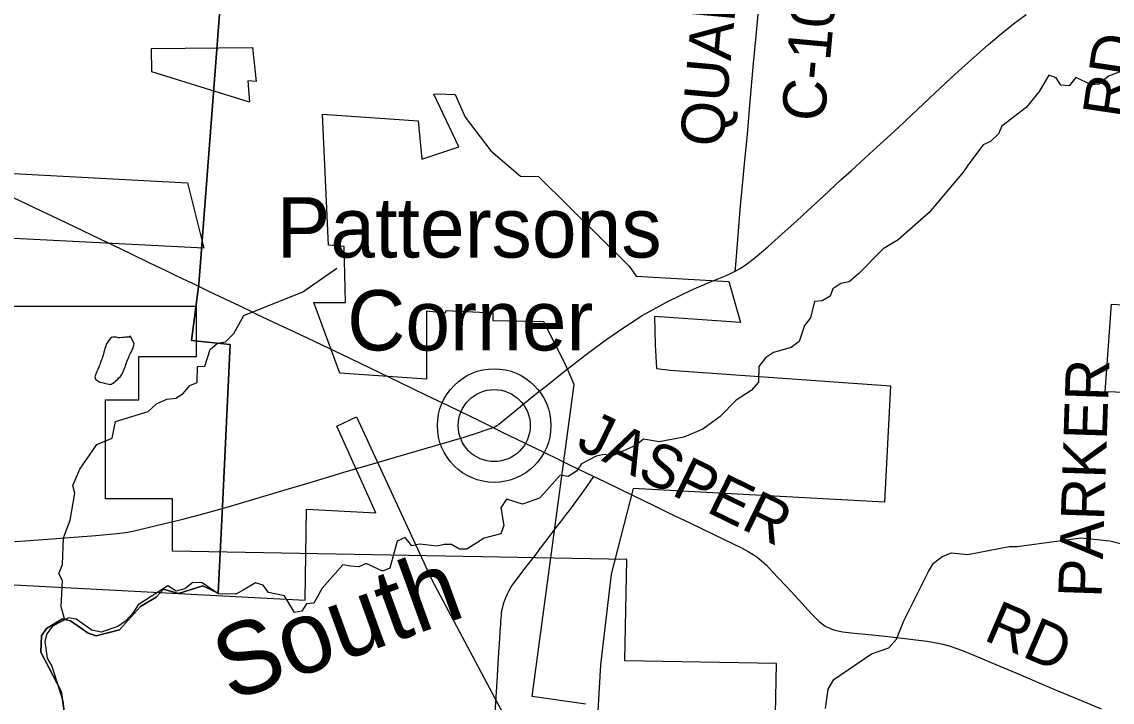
# Model space of a CAD drawing. Extents: x -5.4 to 49.9, y 13.2 to 48.4.
# Drawn here: x 27.015 to 28.445, y 41.82 to 42.711 of the extents above; entities that cross this region are included whole.
import ezdxf

# ---------------------------------------------------------------- set-up
doc = ezdxf.new("R2010")
doc.units = 0
for name, color, linetype in [('GM_X_Corporation', 7, 'Continuous'), ('GM_X_County_Road', 7, 'Continuous'), ('GM_X_County_Road_Text', 7, 'Continuous'), ('GM_X_Minor_Lake', 7, 'Continuous'), ('GM_X_Minor_River', 7, 'Continuous'), ('GM_X_Minor_River_Text', 7, 'Continuous'), ('GM_X_Township', 7, 'Continuous'), ('GM_X_Township_Road_Text', 7, 'Continuous'), ('GM_X_Unincorporated', 7, 'Continuous'), ('GM_X_Unincorporated_Location', 7, 'Continuous'), ('GM_X_Unincorporated_Text', 7, 'Continuous')]:
    doc.layers.add(name, color=color, linetype=linetype)

msp = doc.modelspace()

# ---------------------------------------------------------------- linework, layer by layer
at = {"layer": 'GM_X_Corporation'}
for points in [[(27.3179, 42.6776), (27.3227, 42.6332), (27.3114, 42.6342), (27.3139, 42.6063), (27.1858, 42.6457), (27.1855, 42.6766), (27.3179, 42.6776)], [(27.7547, 41.8177), (27.6842, 41.8275), (27.7383, 42.2266), (27.7396, 42.2365), (27.7326, 42.2523), (27.7276, 42.2635), (27.6995, 42.3184), (27.6331, 42.3196), (27.6333, 42.3298), (27.5711, 42.333), (27.5703, 42.3297), (27.546, 42.3323), (27.546, 42.2431), (27.4321, 42.251), (27.3983, 42.3438), (27.4398, 42.3438), (27.4377, 42.4172), (27.4172, 42.419), (27.4093, 42.5906), (27.5351, 42.5819), (27.5396, 42.5315), (27.5882, 42.5476), (27.5553, 42.6165), (27.5599, 42.617), (27.5835, 42.616), (27.5966, 42.5866)], [(27.5966, 42.5866), (27.63, 42.5423), (27.6693, 42.5093), (27.6928, 42.5086), (27.8115, 42.3913), (27.8208, 42.3784), (27.9422, 42.3712), (27.9575, 42.3177), (27.8449, 42.3255), (27.8455, 42.2886), (27.8472, 42.2574), (27.8654, 42.2549), (28.1544, 42.2346), (28.1464, 42.0821), (27.817, 42.1), (27.7879, 41.9878), (27.7742, 41.8691), (27.7695, 41.7935)], [(26.7591, 42.5258), (27.2326, 42.5005), (27.2539, 42.415), (26.7558, 42.4403), (26.7591, 42.5258)], [(28.0022, 41.7383), (28.0047, 41.8708), (27.8059, 41.8745), (27.8083, 42.007), (27.2127, 42.0179), (27.2127, 42.0867), (27.1248, 42.0867), (27.1248, 42.2164), (27.1687, 42.2164), (27.1687, 42.2732), (27.2441, 42.2732), (27.2441, 42.3385), (26.9242, 42.3385)], [(28.5454, 42.223), (28.4358, 42.2265), (28.4438, 42.3414), (28.5393, 42.3357)], [(26.2655, 42.0542), (26.5579, 42.0391), (26.5676, 42.1776), (26.7474, 42.1619), (26.7396, 41.9878), (27.3866, 41.954), (27.3887, 42.0728), (27.4795, 42.068), (27.4285, 42.1818), (27.4542, 42.1938), (27.5529, 41.9806), (27.6747, 41.7515)]]:
    msp.add_lwpolyline(points, dxfattribs=at)
at = {"layer": 'GM_X_County_Road'}
for points in [[(27.9506, 42.3848), (27.9508, 42.3879), (27.9547, 42.437), (27.9573, 42.4655), (27.9633, 42.5298), (27.9665, 42.5638), (27.9699, 42.6022), (27.9748, 42.6574), (27.9784, 42.6975), (27.9843, 42.7606), (27.99, 42.8237), (28.0003, 42.9413), (28.0078, 43.0236), (28.0101, 43.0491)], [(27.9506, 42.3848), (27.957, 42.3884), (27.9643, 42.3931), (27.9704, 42.3975), (27.9768, 42.4026), (27.9933, 42.4167), (28.016, 42.437), (28.0312, 42.4508), (28.0459, 42.4642), (28.0596, 42.4768), (28.0737, 42.4899), (28.0893, 42.5042), (28.103, 42.5168), (28.12, 42.5322), (28.1315, 42.5427), (28.1503, 42.5598), (28.165, 42.5733), (28.2056, 42.6117), (28.2193, 42.6244), (28.2334, 42.6375), (28.2476, 42.6505), (28.2674, 42.6683), (28.2829, 42.6818), (28.2995, 42.6958), (28.3154, 42.7086), (28.3319, 42.7208)], [(26.5924, 42.678), (26.5999, 42.6744), (26.6448, 42.6531), (26.6945, 42.6289), (26.7398, 42.6071), (26.7807, 42.5876), (26.8083, 42.5746), (26.834, 42.5623), (26.8594, 42.5506), (26.8739, 42.5435), (26.9008, 42.5307), (26.9225, 42.52), (26.9392, 42.5118), (26.974, 42.4954), (27.0313, 42.4683), (27.0627, 42.4533), (27.1166, 42.4277), (27.1357, 42.4186), (27.1569, 42.4083), (27.1826, 42.3958), (27.2039, 42.3856), (27.2146, 42.3806), (27.2331, 42.3717), (27.2381, 42.3693)], [(27.6331, 42.18), (27.6365, 42.1815), (27.6381, 42.1824), (27.6394, 42.1832), (27.6407, 42.1842), (27.6617, 42.2012), (27.6818, 42.2179), (27.6866, 42.2218), (27.7037, 42.2351), (27.7265, 42.2534), (27.7535, 42.2743), (27.7674, 42.2847), (27.7825, 42.2956), (27.8061, 42.3118), (27.8195, 42.3207), (27.8278, 42.3261), (27.843, 42.3346), (27.8605, 42.344), (27.8793, 42.3535), (27.8928, 42.3598), (27.903, 42.3644), (27.9225, 42.3725), (27.938, 42.3788), (27.9443, 42.3816), (27.9505, 42.3847), (27.9506, 42.3848)], [(27.2381, 42.3693), (27.261, 42.3581), (27.2879, 42.3454), (27.3003, 42.3396), (27.3182, 42.331), (27.3214, 42.3294)], [(27.3214, 42.3294), (27.3377, 42.3214), (27.3574, 42.3122), (27.3726, 42.3052), (27.4344, 42.276), (27.4708, 42.2585), (27.5106, 42.2394), (27.5447, 42.2229), (27.575, 42.2083), (27.6158, 42.1886), (27.6331, 42.18)], [(27.2778, 42.074), (27.2843, 42.0758), (27.3355, 42.0909), (27.3617, 42.0988), (27.3933, 42.1081), (27.4361, 42.1209), (27.4755, 42.1325), (27.5201, 42.1457), (27.5953, 42.1674), (27.6155, 42.1737), (27.6214, 42.1759), (27.6331, 42.18)], [(27.6331, 42.18), (27.6451, 42.1738), (27.6743, 42.1601), (27.7005, 42.1472), (27.7184, 42.1385), (27.7334, 42.1312), (27.7552, 42.1205), (27.7654, 42.1157)], [(27.6337, 41.7711), (27.6367, 41.8207), (27.6383, 41.8468), (27.6399, 41.8709), (27.6408, 41.8858), (27.6412, 41.8914), (27.6419, 41.9038), (27.6425, 41.9125), (27.6429, 41.9186), (27.6431, 41.9217), (27.6433, 41.9268), (27.6437, 41.9304), (27.644, 41.9341), (27.6443, 41.9372), (27.6448, 41.9401), (27.6453, 41.9429), (27.6458, 41.9449), (27.6464, 41.9472), (27.6473, 41.9501), (27.6499, 41.9571), (27.6521, 41.9621), (27.6543, 41.9665), (27.657, 41.9713), (27.6594, 41.9749), (27.6641, 41.9813), (27.675, 41.9956), (27.6895, 42.0142), (27.6921, 42.0177), (27.6936, 42.0197), (27.6969, 42.0242), (27.6992, 42.0271), (27.7026, 42.0315), (27.7147, 42.0472), (27.7182, 42.0516), (27.7217, 42.056), (27.7296, 42.0663), (27.7334, 42.0713), (27.7359, 42.0748), (27.7429, 42.0843), (27.7465, 42.0893), (27.7491, 42.0928), (27.752, 42.0969), (27.7546, 42.1003), (27.7573, 42.1044), (27.7594, 42.1075), (27.7604, 42.1089), (27.7654, 42.1157)], [(27.7654, 42.1157), (27.7793, 42.1091), (27.8016, 42.0983), (27.8455, 42.077)], [(27.0057, 42.0307), (27.0201, 42.0316), (27.0659, 42.0348), (27.1123, 42.0385), (27.1397, 42.041), (27.1476, 42.0419), (27.1537, 42.0428), (27.1648, 42.0449), (27.1912, 42.0515), (27.2262, 42.0601), (27.2562, 42.0679), (27.2778, 42.074)], [(27.8455, 42.077), (27.8631, 42.0684), (27.891, 42.0549), (27.9224, 42.0398), (27.9587, 42.0222), (27.9676, 42.0176), (27.9741, 42.0138), (27.9792, 42.0102), (27.9846, 42.0059), (27.9915, 41.9995), (27.9997, 41.991), (28.0242, 41.9645), (28.0335, 41.9545), (28.0507, 41.9357), (28.0554, 41.9309), (28.0609, 41.9259), (28.0645, 41.9228), (28.068, 41.9203), (28.071, 41.9186), (28.0736, 41.9174), (28.0772, 41.916), (28.0814, 41.9147), (28.0853, 41.9138), (28.0919, 41.9125), (28.1028, 41.911), (28.1395, 41.9074), (28.1661, 41.9046), (28.1839, 41.9024), (28.2024, 41.8999), (28.2147, 41.8978), (28.2227, 41.8961), (28.2311, 41.8938), (28.2412, 41.8905), (28.2517, 41.8866), (28.2718, 41.8783), (28.2924, 41.8694), (28.3187, 41.8584), (28.3685, 41.8374), (28.4063, 41.8214), (28.4304, 41.8113)]]:
    msp.add_lwpolyline(points, dxfattribs=at)
at = {"layer": 'GM_X_Minor_Lake'}
msp.add_lwpolyline([(27.1576, 42.2997), (27.1561, 42.2985), (27.1538, 42.2982), (27.1512, 42.2982), (27.1493, 42.2978), (27.1474, 42.2979), (27.1439, 42.2975), (27.1417, 42.2975), (27.1394, 42.2983), (27.1375, 42.2983), (27.1348, 42.2984), (27.1322, 42.298), (27.1299, 42.295), (27.1264, 42.2897), (27.1248, 42.2856), (27.1241, 42.2833), (27.1237, 42.2814), (27.1229, 42.2787), (27.1225, 42.2765), (27.1217, 42.2746), (27.1209, 42.2727), (27.1205, 42.2704), (27.1193, 42.2678), (27.1182, 42.264), (27.1174, 42.2621), (27.1166, 42.2602), (27.115, 42.256), (27.1139, 42.2542), (27.1131, 42.2523), (27.1108, 42.2462), (27.1119, 42.2432), (27.1149, 42.2412), (27.1175, 42.2393), (27.1202, 42.2389), (27.1232, 42.2381), (27.127, 42.2373), (27.1296, 42.2369), (27.1315, 42.2365), (27.1342, 42.2376), (27.1361, 42.2391), (27.138, 42.2406), (27.1411, 42.2432), (27.1426, 42.2451), (27.1445, 42.247), (27.1469, 42.2504), (27.148, 42.253), (27.15, 42.2576), (27.1511, 42.2602), (27.1515, 42.2625), (27.1539, 42.2685), (27.1554, 42.2716), (27.1558, 42.2738), (27.1574, 42.2765), (27.1585, 42.2788), (27.1601, 42.2818), (27.1612, 42.2837), (27.1621, 42.2878), (27.1625, 42.2897), (27.1576, 42.2997)], dxfattribs=at)
at = {"layer": 'GM_X_Minor_River'}
for points in [[(28.4608, 42.6479), (28.4402, 42.6403), (28.428, 42.6298), (28.4177, 42.6288), (28.397, 42.6386), (28.3885, 42.6274), (28.3775, 42.6283), (28.3716, 42.6379), (28.3618, 42.6414), (28.3493, 42.62), (28.3319, 42.599), (28.3001, 42.5748), (28.2958, 42.5646), (28.2854, 42.5545), (28.2758, 42.5501), (28.2584, 42.5269), (28.2495, 42.5145), (28.2047, 42.4616), (28.1643, 42.4258), (28.1444, 42.414), (28.1121, 42.3814), (28.0998, 42.371), (28.0891, 42.3685), (28.0788, 42.3618), (28.0752, 42.352), (28.0645, 42.3457), (28.0546, 42.3451), (28.0494, 42.3236), (28.0413, 42.3134), (28.0345, 42.2927), (28.0241, 42.2849), (28.0009, 42.2784), (27.9902, 42.2713), (27.9817, 42.2601), (27.981, 42.2392), (27.9717, 42.2283), (27.9518, 42.2157), (27.931, 42.1944), (27.908, 42.1777), (27.8832, 42.1674), (27.8508, 42.1611), (27.8304, 42.1648), (27.8208, 42.157), (27.7895, 42.1427), (27.7789, 42.1447), (27.7683, 42.1426), (27.7492, 42.1326), (27.7426, 42.1229), (27.7315, 42.1158), (27.7213, 42.1175), (27.7035, 42.0977), (27.6942, 42.0872), (27.6718, 42.0795), (27.6506, 42.0859), (27.6432, 42.0747), (27.6471, 42.0515), (27.6431, 42.0405), (27.6214, 42.0351), (27.5988, 42.0207), (27.5889, 42.0205), (27.5788, 42.0267), (27.5689, 42.0265), (27.5594, 42.0247), (27.5371, 42.0273), (27.5268, 42.0248), (27.5179, 42.036), (27.5072, 42.0312), (27.4979, 41.9956), (27.488, 41.992), (27.4669, 42.0018), (27.457, 41.9974), (27.446, 41.9983), (27.4362, 42), (27.4092, 41.9693), (27.3983, 41.9497), (27.3884, 41.9491), (27.3822, 41.9393), (27.3727, 41.9376), (27.3597, 41.9594), (27.3389, 41.9639), (27.3319, 41.9735), (27.3217, 41.9767), (27.3056, 41.9671), (27.2957, 41.9615), (27.2729, 41.9619), (27.2519, 41.9766)], [(27.0717, 41.9282), (27.0668, 41.9449), (27.0684, 41.9794), (27.0637, 41.9889), (27.0684, 42.0006), (27.0701, 42.0355), (27.0787, 42.0585), (27.0846, 42.0941), (27.0821, 42.104), (27.0915, 42.1255), (27.1136, 42.1578), (27.1339, 42.1659), (27.138, 42.1878), (27.181, 42.2008), (27.1918, 42.2109), (27.2056, 42.2172), (27.217, 42.2185), (27.2269, 42.2244), (27.2354, 42.2349), (27.2453, 42.239), (27.2456, 42.2598), (27.2551, 42.2604), (27.2623, 42.282), (27.2719, 42.2906), (27.2825, 42.2923), (27.2933, 42.3031), (27.3062, 42.3265), (27.3837, 42.3579), (27.4285, 42.3888)], [(28.0692, 41.812), (28.0726, 41.837), (28.0797, 41.8498), (28.1295, 41.8836), (28.152, 41.8912), (28.162, 41.9025), (28.1718, 41.9266), (28.2039, 41.9914), (28.2105, 42.0023), (28.2221, 42.0112), (28.2343, 42.0156), (28.2558, 42.0138), (28.3098, 42.024), (28.3205, 42.0242), (28.4044, 42.0354), (28.4419, 42.0314), (28.4646, 42.0258)], [(27.2519, 41.9766), (27.2394, 41.9768), (27.2291, 41.9686), (27.2176, 41.9657), (27.2067, 41.9724), (27.1677, 41.9479), (27.1607, 41.9366), (27.151, 41.9261), (27.1411, 41.9195), (27.1194, 41.9118), (27.1069, 41.9147), (27.0866, 41.929), (27.0764, 41.9307), (27.0554, 41.9196), (27.048, 41.9099), (27.0456, 41.8996), (27.0483, 41.878), (27.0546, 41.8672), (27.0691, 41.8219), (27.0714, 41.8017)]]:
    msp.add_lwpolyline(points, dxfattribs=at)
at = {"layer": 'GM_X_Township'}
for points in [[(27.0717, 41.8029), (27.0668, 41.8344), (27.0401, 41.8857), (27.0411, 41.9069), (27.0477, 41.9167), (27.0687, 41.9294), (27.0789, 41.9266), (27.1023, 41.9107), (27.1128, 41.9072), (27.1433, 41.9151), (27.171, 41.9456), (27.1913, 41.9578), (27.2009, 41.968), (27.2209, 41.9624), (27.2525, 41.9727), (27.2729, 41.9629), (27.2783, 42.0764), (27.2883, 42.2889), (27.2379, 42.2941), (27.2472, 42.3677), (27.2901, 42.9269)], [(27.2901, 42.9269), (27.2472, 42.3677), (27.2379, 42.2941), (27.2883, 42.2889), (27.2783, 42.0764), (27.2729, 41.9629), (27.2525, 41.9727), (27.2209, 41.9624), (27.2009, 41.968), (27.1913, 41.9578), (27.171, 41.9456), (27.1433, 41.9151), (27.1128, 41.9072), (27.1023, 41.9107), (27.0789, 41.9266), (27.0687, 41.9294), (27.0477, 41.9167), (27.0411, 41.9069), (27.0401, 41.8857), (27.0668, 41.8344), (27.0717, 41.8029)]]:
    msp.add_lwpolyline(points, dxfattribs=at)
at = {"layer": 'GM_X_Unincorporated'}
for radius in [0.0744, 0.0472]:
    msp.add_circle((27.6346, 42.1825), radius, dxfattribs=at)
at = {"layer": 'GM_X_Unincorporated_Location'}
msp.add_line((27.6346, 42.1825), (27.6346, 42.1825), dxfattribs=at)

# ---------------------------------------------------------------- texts
at = {"layer": 'GM_X_County_Road_Text'}
for s, rotation, p in [('QUARRY', 84.8172, (27.9344, 42.5462)), ('C-100', 84.7805, (28.0676, 42.5793)), ('JASPER', 334.0399, (27.7402, 42.1534)), ('RD', 336.7376, (28.2747, 41.9023))]:
    msp.add_text(s, height=0.05682, rotation=rotation, dxfattribs=at).set_placement(p)
at = {"layer": 'GM_X_Minor_River_Text'}
msp.add_text('South', height=0.09469, rotation=19.999, dxfattribs=at).set_placement((27.2886, 41.8203))
at = {"layer": 'GM_X_Township_Road_Text'}
for s, rotation, p in [('RD', 81.5878, (28.462, 42.5832)), ('PARKER', 88.0961, (28.4309, 41.9564))]:
    msp.add_text(s, height=0.05682, rotation=rotation, dxfattribs=at).set_placement(p)
at = {"layer": 'GM_X_Unincorporated_Text'}
for s, p in [('Pattersons', (27.3493, 42.4026)), ('Corner', (27.4418, 42.2809))]:
    msp.add_text(s, height=0.07898, rotation=0, dxfattribs=at).set_placement(p)

doc.saveas('drawing.dxf')
